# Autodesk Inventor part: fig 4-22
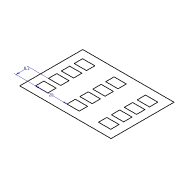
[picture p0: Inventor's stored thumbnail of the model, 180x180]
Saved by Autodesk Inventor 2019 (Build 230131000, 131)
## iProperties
Created: 2004-05
Part Number: fig 4-22
Document SubType Name: Modeling
Designer: CADCIM Technologies
Manufacturer: Standard
Standards Organization: Custom
Density: 1 g/cm^3
Material: Generic
Appearance: Default
Author: CADCIM Technologies
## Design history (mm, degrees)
sketch "Sketch1"
  geometry: L1 (7.752, 6.176)-(65.752, 6.176); L2 (65.752, 6.176)-(65.752, 46.176); L3 (65.752, 46.176)-(7.752, 46.176); L4 (7.752, 46.176)-(7.752, 6.176); L5 (12.752, 11.176)-(20.543, 11.176); L6 (20.543, 11.176)-(20.543, 16.473); L7 (20.543, 16.473)-(12.752, 16.473); L8 (12.752, 16.473)-(12.752, 11.176); L9 (32.752, 11.176)-(40.543, 11.176); L10 (40.543, 11.176)-(40.543, 16.473); L11 (40.543, 16.473)-(32.752, 16.473); L12 (32.752, 16.473)-(32.752, 11.176); L13 (52.752, 11.176)-(60.543, 11.176); L14 (60.543, 11.176)-(60.543, 16.473); L15 (60.543, 16.473)-(52.752, 16.473); L16 (52.752, 16.473)-(52.752, 11.176); L17 (12.752, 19.376)-(20.543, 19.376); L18 (20.543, 19.376)-(20.543, 24.673); L19 (20.543, 24.673)-(12.752, 24.673); L20 (12.752, 24.673)-(12.752, 19.376); L21 (32.752, 19.376)-(40.543, 19.376); L22 (40.543, 19.376)-(40.543, 24.673); L23 (40.543, 24.673)-(32.752, 24.673); L24 (32.752, 24.673)-(32.752, 19.376); L25 (52.752, 19.376)-(60.543, 19.376); L26 (60.543, 19.376)-(60.543, 24.673); L27 (60.543, 24.673)-(52.752, 24.673); L28 (52.752, 24.673)-(52.752, 19.376); L29 (12.752, 27.576)-(20.543, 27.576); L30 (20.543, 27.576)-(20.543, 32.873); L31 (20.543, 32.873)-(12.752, 32.873); L32 (12.752, 32.873)-(12.752, 27.576); L33 (32.752, 27.576)-(40.543, 27.576); L34 (40.543, 27.576)-(40.543, 32.873); L35 (40.543, 32.873)-(32.752, 32.873); L36 (32.752, 32.873)-(32.752, 27.576); L37 (52.752, 27.576)-(60.543, 27.576); L38 (60.543, 27.576)-(60.543, 32.873); L39 (60.543, 32.873)-(52.752, 32.873); L40 (52.752, 32.873)-(52.752, 27.576); L41 (12.752, 35.776)-(20.543, 35.776); L42 (20.543, 35.776)-(20.543, 41.073); L43 (20.543, 41.073)-(12.752, 41.073); L44 (12.752, 41.073)-(12.752, 35.776); L45 (32.752, 35.776)-(40.543, 35.776); L46 (40.543, 35.776)-(40.543, 41.073); L47 (40.543, 41.073)-(32.752, 41.073); L48 (32.752, 41.073)-(32.752, 35.776); L49 (52.752, 35.776)-(60.543, 35.776); L50 (60.543, 35.776)-(60.543, 41.073); L51 (60.543, 41.073)-(52.752, 41.073); L52 (52.752, 41.073)-(52.752, 35.776)
  constraints: 104 end point, 4 parallel, 3 horizontal, 2 perpendicular, 1 vertical, 88 other
  dimensions: "d14" = 20 distance of L5.start L9.start; "d17" = 8.2 distance of L5.start L17.start
